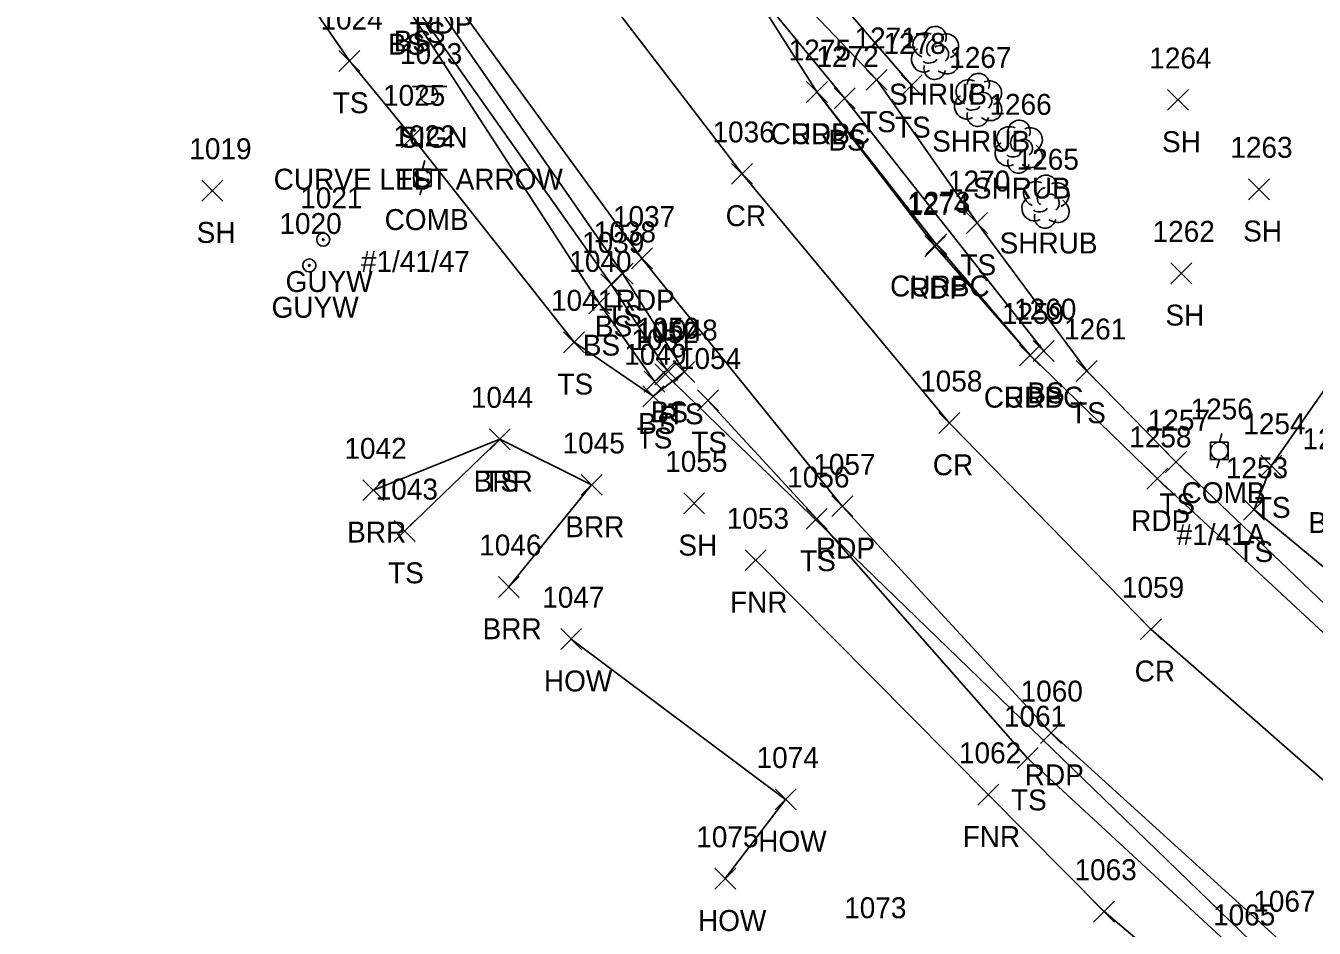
# Model space of a CAD drawing. Extents: x 1761340 to 1763889, y 696770 to 706023.
# Drawn here: x 1761355.7 to 1761478.8, y 700913.9 to 701000.1 of the extents above; entities that cross this region are included whole.
import ezdxf

# ---------------------------------------------------------------- set-up
doc = ezdxf.new("R2010")
doc.units = 0
for name, color, linetype in [('D_A', 7, 'Continuous'), ('D_I', 7, 'Continuous'), ('D_TIC', 7, 'Continuous'), ('DCP', 7, 'Continuous'), ('L_A', 7, 'Continuous'), ('L_I', 7, 'Continuous'), ('L_TIC', 7, 'Continuous'), ('LABL', 7, 'Continuous'), ('LBC', 7, 'Continuous'), ('LELB', 7, 'Continuous'), ('LFNC', 7, 'Continuous'), ('LSH', 7, 'Continuous'), ('P_A', 7, 'Continuous'), ('P_I', 7, 'Continuous'), ('P_TIC', 7, 'Continuous'), ('PET', 7, 'Continuous'), ('PRC', 7, 'Continuous'), ('R_A', 7, 'Continuous'), ('R_I', 7, 'Continuous'), ('R_TIC', 7, 'Continuous'), ('RC', 7, 'Continuous'), ('S_A', 7, 'Continuous'), ('S_C', 7, 'Continuous'), ('S_I', 7, 'Continuous'), ('SSGN', 7, 'Continuous'), ('U_A', 7, 'Continuous'), ('U_C', 7, 'Continuous'), ('U_I', 7, 'Continuous'), ('UP', 7, 'Continuous'), ('UPGW', 7, 'Continuous')]:
    doc.layers.add(name, color=color, linetype=linetype)

msp = doc.modelspace()

# ---------------------------------------------------------------- linework, layer by layer
at = {"layer": 'D_TIC'}
for points in [[(1761415.81, 700965.84), (1761417.81, 700967.84)], [(1761417.81, 700965.84), (1761415.81, 700967.84)]]:
    msp.add_lwpolyline(points, dxfattribs=at)
at = {"layer": 'DCP'}
msp.add_lwpolyline([(1761416.81, 700966.84), (1761514.71, 700872.07)], dxfattribs=at)
at = {"layer": 'L_TIC'}
for points in [[(1761385.62, 700995.79), (1761387.62, 700997.79)], [(1761387.62, 700995.79), (1761385.62, 700997.79)], [(1761436.01, 700993.98), (1761438.01, 700995.98)], [(1761438.01, 700993.98), (1761436.01, 700995.98)], [(1761439.34, 700993.46), (1761441.34, 700995.46)], [(1761441.34, 700993.46), (1761439.34, 700995.46)], [(1761432.93, 700992.22), (1761434.93, 700994.22)], [(1761434.93, 700992.22), (1761432.93, 700994.22)], [(1761464.78, 700992.07), (1761466.78, 700994.07)], [(1761466.78, 700992.07), (1761464.78, 700994.07)], [(1761391.6, 700988.5), (1761393.6, 700990.5)], [(1761393.6, 700988.5), (1761391.6, 700990.5)], [(1761372.53, 700983.4), (1761374.53, 700985.4)], [(1761374.53, 700983.4), (1761372.53, 700985.4)], [(1761472.53, 700983.53), (1761474.53, 700985.53)], [(1761474.53, 700983.53), (1761472.53, 700985.53)], [(1761445.59, 700980.31), (1761447.59, 700982.31)], [(1761447.59, 700980.31), (1761445.59, 700982.31)], [(1761411.73, 700975.45), (1761413.73, 700977.45)], [(1761413.73, 700975.45), (1761411.73, 700977.45)], [(1761465.1, 700975.5), (1761467.1, 700977.5)], [(1761467.1, 700975.5), (1761465.1, 700977.5)], [(1761410.63, 700974.45), (1761412.63, 700976.45)], [(1761412.63, 700974.45), (1761410.63, 700976.45)], [(1761409.48, 700972.63), (1761411.48, 700974.63)], [(1761411.48, 700972.63), (1761409.48, 700974.63)], [(1761407.08, 700968.91), (1761409.08, 700970.91)], [(1761409.08, 700968.91), (1761407.08, 700970.91)], [(1761451.96, 700968.07), (1761453.96, 700970.07)], [(1761453.96, 700968.07), (1761451.96, 700970.07)], [(1761415.96, 700966.25), (1761417.96, 700968.25)], [(1761417.96, 700966.25), (1761415.96, 700968.25)], [(1761417.63, 700966.07), (1761419.63, 700968.07)], [(1761419.63, 700966.07), (1761417.63, 700968.07)], [(1761456.07, 700966.17), (1761458.07, 700968.17)], [(1761458.07, 700966.17), (1761456.07, 700968.17)], [(1761414.77, 700965.15), (1761416.77, 700967.15)], [(1761416.77, 700965.15), (1761414.77, 700967.15)], [(1761414.77, 700965.15), (1761416.77, 700967.15)], [(1761416.77, 700965.15), (1761414.77, 700967.15)], [(1761414.65, 700963.75), (1761416.65, 700965.75)], [(1761416.65, 700963.75), (1761414.65, 700965.75)], [(1761414.65, 700963.75), (1761416.65, 700965.75)], [(1761416.65, 700963.75), (1761414.65, 700965.75)], [(1761419.87, 700963.35), (1761421.87, 700965.35)], [(1761421.87, 700963.35), (1761419.87, 700965.35)], [(1761399.99, 700959.64), (1761401.99, 700961.64)], [(1761401.99, 700959.64), (1761399.99, 700961.64)], [(1761399.99, 700959.64), (1761401.99, 700961.64)], [(1761401.99, 700959.64), (1761399.99, 700961.64)], [(1761464.59, 700957.47), (1761466.59, 700959.47)], [(1761466.59, 700957.47), (1761464.59, 700959.47)], [(1761473.72, 700957.12), (1761475.72, 700959.12)], [(1761475.72, 700957.12), (1761473.72, 700959.12)], [(1761408.76, 700955.28), (1761410.76, 700957.28)], [(1761410.76, 700955.28), (1761408.76, 700957.28)], [(1761387.91, 700954.77), (1761389.91, 700956.77)], [(1761389.91, 700954.77), (1761387.91, 700956.77)], [(1761418.56, 700953.52), (1761420.56, 700955.52)], [(1761420.56, 700953.52), (1761418.56, 700955.52)], [(1761472.06, 700952.91), (1761474.06, 700954.91)], [(1761474.06, 700952.91), (1761472.06, 700954.91)], [(1761430.27, 700952.03), (1761432.27, 700954.03)], [(1761432.27, 700952.03), (1761430.27, 700954.03)], [(1761390.9, 700950.87), (1761392.9, 700952.87)], [(1761392.9, 700950.87), (1761390.9, 700952.87)], [(1761424.44, 700948.08), (1761426.44, 700950.08)], [(1761426.44, 700948.08), (1761424.44, 700950.08)], [(1761400.85, 700945.53), (1761402.85, 700947.53)], [(1761402.85, 700945.53), (1761400.85, 700947.53)], [(1761406.81, 700940.54), (1761408.81, 700942.54)], [(1761408.81, 700940.54), (1761406.81, 700942.54)], [(1761450.42, 700929.17), (1761452.42, 700931.17)], [(1761452.42, 700929.17), (1761450.42, 700931.17)], [(1761446.68, 700925.67), (1761448.68, 700927.67)], [(1761448.68, 700925.67), (1761446.68, 700927.67)], [(1761427.3, 700925.22), (1761429.3, 700927.22)], [(1761429.3, 700925.22), (1761427.3, 700927.22)], [(1761421.53, 700917.65), (1761423.53, 700919.65)], [(1761423.53, 700917.65), (1761421.53, 700919.65)], [(1761457.72, 700914.5), (1761459.72, 700916.5)], [(1761459.72, 700914.5), (1761457.72, 700916.5)]]:
    msp.add_lwpolyline(points, dxfattribs=at)
at = {"layer": 'LABL'}
msp.add_lwpolyline([(1761388.91, 700955.77), (1761400.99, 700960.64), (1761409.76, 700956.28), (1761401.85, 700946.53)], dxfattribs=at)
at = {"layer": 'LBC'}
msp.add_lwpolyline([(1761407.81, 700941.54), (1761428.3, 700926.22), (1761422.53, 700918.65)], dxfattribs=at)
at = {"layer": 'LELB'}
for points in [[(1761440.34, 700994.46), (1761428.93, 701007.72), (1761425.32, 701020.81), (1761405.58, 701045), (1761388.99, 701070.94)], [(1761510.82, 700921.94), (1761487.03, 700937.99), (1761465.59, 700958.47), (1761457.07, 700967.17), (1761446.59, 700981.31), (1761437.01, 700994.98), (1761426.19, 701006.36), (1761420.48, 701017.58), (1761403.34, 701042.42), (1761383.02, 701066.87)], [(1761360.86, 701050.4), (1761380.33, 701022.73), (1761393.97, 701003.51), (1761412.73, 700976.45), (1761418.63, 700967.07), (1761415.65, 700964.75)], [(1761359.9, 701049.49), (1761378.89, 701021.46), (1761392.41, 701002.69), (1761411.63, 700975.45), (1761416.96, 700967.25), (1761415.77, 700966.15)], [(1761357.7, 701048.72), (1761378.05, 701020.95), (1761391.86, 701002.38), (1761410.48, 700973.63), (1761415.77, 700966.15)], [(1761355.69, 701047.71), (1761364.73, 701030.03), (1761371.68, 701018.45), (1761386.62, 700996.79), (1761392.6, 700989.5), (1761408.08, 700969.91), (1761415.65, 700964.75)], [(1761452.96, 700969.07), (1761433.93, 700993.22), (1761424.05, 701005.24)], [(1761506.71, 700926.07), (1761489.79, 700940.08), (1761473.06, 700953.91), (1761474.72, 700958.12), (1761484.47, 700972.09)], [(1761420.87, 700964.35), (1761431.27, 700953.03), (1761451.42, 700930.17), (1761471.96, 700911.18)], [(1761391.9, 700951.87), (1761400.99, 700960.64)]]:
    msp.add_lwpolyline(points, dxfattribs=at)
at = {"layer": 'LFNC'}
msp.add_lwpolyline([(1761425.44, 700949.08), (1761447.68, 700926.67), (1761458.72, 700915.5), (1761471.96, 700904.31)], dxfattribs=at)
at = {"layer": 'LSH'}
for p, q in [((1761442.55, 700997.61), (1761442.55, 700997.61)), ((1761442.55, 700997.61), (1761442.55, 700997.61)), ((1761446.67, 700993.12), (1761446.67, 700993.12)), ((1761446.67, 700993.12), (1761446.67, 700993.12)), ((1761450.56, 700988.64), (1761450.56, 700988.64)), ((1761450.56, 700988.64), (1761450.56, 700988.64)), ((1761453.11, 700983.39), (1761453.11, 700983.39)), ((1761453.11, 700983.39), (1761453.11, 700983.39))]:
    msp.add_line(p, q, dxfattribs=at)
for centre in [(1761442.6, 700999.04), (1761446.72, 700994.55), (1761450.61, 700990.07), (1761453.16, 700984.83)]:
    msp.add_arc(centre, 1.05, 335.5272, 180.9563, dxfattribs=at)
for centre, major_axis, ratio, start_param, end_param in [((1761441.76, 700998.27), (1.21, -0.51), 0.895232, 1.570796, 4.712389), ((1761442.34, 700998.06), (-0.208, -0.792), 0.645439, 3.141593, 6.283185), ((1761443.59, 700998.19), (-1.14, -0.48), 0.949671, 1.570796, 4.712389), ((1761441.47, 700996.9), (0.58, -1.04), 0.959034, 3.141593, 6.283185), ((1761443.05, 700997.44), (-0.5, 0.667), 0.989748, 3.141593, 6.283185), ((1761443.55, 700996.77), (-1.09, 0.79), 0.841452, 1.570796, 4.712389), ((1761442.55, 700996.11), (0.26, 1.06), 0.942809, 1.570796, 4.712389), ((1761442.09, 700996.86), (-0.625, -0.083), 0.423636, 0, 3.141593), ((1761445.88, 700993.79), (1.21, -0.51), 0.895232, 1.570796, 4.712389), ((1761447.71, 700993.7), (-1.14, -0.48), 0.949671, 1.570796, 4.712389), ((1761446.46, 700993.58), (-0.208, -0.792), 0.645439, 3.141593, 6.283185), ((1761447.17, 700992.95), (-0.5, 0.667), 0.989748, 3.141593, 6.283185), ((1761445.59, 700992.41), (0.58, -1.04), 0.959034, 3.141593, 6.283185), ((1761447.67, 700992.29), (-1.09, 0.79), 0.841452, 1.570796, 4.712389), ((1761446.67, 700991.62), (0.26, 1.06), 0.942809, 1.570796, 4.712389), ((1761446.21, 700992.37), (-0.625, -0.083), 0.423636, 0, 3.141593), ((1761449.77, 700989.31), (1.21, -0.51), 0.895232, 1.570796, 4.712389), ((1761451.6, 700989.22), (-1.14, -0.48), 0.949671, 1.570796, 4.712389), ((1761449.48, 700987.93), (0.58, -1.04), 0.959034, 3.141593, 6.283185), ((1761450.35, 700989.1), (-0.208, -0.792), 0.645439, 3.141593, 6.283185), ((1761451.06, 700988.47), (-0.5, 0.667), 0.989748, 3.141593, 6.283185), ((1761450.1, 700987.89), (-0.625, -0.083), 0.423636, 0, 3.141593), ((1761451.56, 700987.81), (-1.09, 0.79), 0.841452, 1.570796, 4.712389), ((1761450.56, 700987.14), (0.26, 1.06), 0.942809, 1.570796, 4.712389), ((1761452.32, 700984.06), (1.21, -0.51), 0.895232, 1.570796, 4.712389), ((1761454.15, 700983.97), (-1.14, -0.48), 0.949671, 1.570796, 4.712389), ((1761452.9, 700983.85), (-0.208, -0.792), 0.645439, 3.141593, 6.283185), ((1761453.61, 700983.22), (-0.5, 0.667), 0.989748, 3.141593, 6.283185), ((1761452.03, 700982.68), (0.58, -1.04), 0.959034, 3.141593, 6.283185), ((1761452.65, 700982.64), (-0.625, -0.083), 0.423636, 0, 3.141593), ((1761454.11, 700982.56), (-1.09, 0.79), 0.841452, 1.570796, 4.712389), ((1761453.11, 700981.89), (0.26, 1.06), 0.942809, 1.570796, 4.712389)]:
    msp.add_ellipse(centre, major_axis=major_axis, ratio=ratio, start_param=start_param, end_param=end_param, dxfattribs=at)
at = {"layer": 'P_TIC'}
for points in [[(1761430.29, 700992.83), (1761432.29, 700994.83)], [(1761432.29, 700992.83), (1761430.29, 700994.83)], [(1761423.14, 700985), (1761425.14, 700987)], [(1761425.14, 700985), (1761423.14, 700987)], [(1761441.59, 700978.07), (1761443.59, 700980.07)], [(1761443.59, 700978.07), (1761441.59, 700980.07)], [(1761413.57, 700976.92), (1761415.57, 700978.92)], [(1761415.57, 700976.92), (1761413.57, 700978.92)], [(1761450.66, 700967.66), (1761452.66, 700969.66)], [(1761452.66, 700967.66), (1761450.66, 700969.66)], [(1761442.93, 700961.2), (1761444.93, 700963.2)], [(1761444.93, 700961.2), (1761442.93, 700963.2)], [(1761462.82, 700955.86), (1761464.82, 700957.86)], [(1761464.82, 700955.86), (1761462.82, 700957.86)], [(1761432.71, 700953.24), (1761434.71, 700955.24)], [(1761434.71, 700953.24), (1761432.71, 700955.24)], [(1761462.21, 700941.49), (1761464.21, 700943.49)], [(1761464.21, 700941.49), (1761462.21, 700943.49)], [(1761452.66, 700931.57), (1761454.66, 700933.57)], [(1761454.66, 700931.57), (1761452.66, 700933.57)]]:
    msp.add_lwpolyline(points, dxfattribs=at)
at = {"layer": 'PET'}
for points in [[(1761565.69, 700887.32), (1761551.93, 700894.01), (1761537.2, 700902.21), (1761507.2, 700921.56), (1761485.83, 700936.45), (1761463.82, 700956.86), (1761451.66, 700968.66), (1761442.59, 700979.07), (1761431.29, 700993.83), (1761424.05, 701005.24), (1761416.58, 701016.18), (1761400.04, 701039.88), (1761381.47, 701065.28)], [(1761361.55, 701051.07), (1761381.35, 701023.89), (1761395.32, 701004.39), (1761414.57, 700977.92), (1761433.71, 700954.24), (1761453.66, 700932.57), (1761475.8, 700912.49), (1761486.98, 700903.81), (1761500.92, 700894.3), (1761527.65, 700879.06), (1761551.01, 700866.82), (1761575.84, 700857.11)]]:
    msp.add_lwpolyline(points, dxfattribs=at)
at = {"layer": 'PRC'}
msp.add_lwpolyline([(1761371.66, 701058.14), (1761390.63, 701031.26), (1761404.65, 701011.45), (1761424.14, 700986), (1761443.93, 700962.2), (1761463.21, 700942.49), (1761486.68, 700921.95), (1761508.06, 700906.42), (1761533.51, 700890.82), (1761557.04, 700878.89), (1761580.26, 700869.03), (1761600.69, 700862.06)], dxfattribs=at)
at = {"layer": 'R_TIC'}
for points in [[(1761430.29, 700992.83), (1761432.29, 700994.83)], [(1761432.29, 700992.83), (1761430.29, 700994.83)], [(1761441.69, 700978.28), (1761443.69, 700980.28)], [(1761443.69, 700978.28), (1761441.69, 700980.28)], [(1761450.66, 700967.66), (1761452.66, 700969.66)], [(1761452.66, 700967.66), (1761450.66, 700969.66)]]:
    msp.add_lwpolyline(points, dxfattribs=at)
at = {"layer": 'RC'}
msp.add_lwpolyline([(1761451.66, 700968.66), (1761442.69, 700979.28), (1761431.29, 700993.83)], dxfattribs=at)
at = {"layer": 'SSGN'}
for p, q in [((1761392.6, 700994.35), (1761395.93, 700994.35)), ((1761394.25, 700993.52), (1761394.25, 700993.52))]:
    msp.add_line(p, q, dxfattribs=at)
msp.add_circle((1761394.25, 700993.52), 0.833, dxfattribs=at)
at = {"layer": 'UP'}
for p, q in [((1761392.76, 700984.79), (1761392.76, 700986.46)), ((1761392.76, 700986.46), (1761394.43, 700986.46)), ((1761393.84, 700987.29), (1761393.59, 700986.46)), ((1761394.43, 700986.46), (1761394.43, 700984.79)), ((1761393.59, 700985.63), (1761393.59, 700985.63)), ((1761394.43, 700984.79), (1761392.76, 700984.79)), ((1761393.34, 700983.96), (1761393.59, 700984.79)), ((1761469.99, 700961.19), (1761469.74, 700960.36)), ((1761468.91, 700958.69), (1761468.91, 700960.36)), ((1761468.91, 700960.36), (1761470.57, 700960.36)), ((1761469.74, 700959.53), (1761469.74, 700959.53)), ((1761470.57, 700960.36), (1761470.57, 700958.69)), ((1761470.57, 700958.69), (1761468.91, 700958.69)), ((1761469.49, 700957.86), (1761469.74, 700958.69))]:
    msp.add_line(p, q, dxfattribs=at)
for centre in [(1761393.59, 700985.63), (1761469.74, 700959.53)]:
    msp.add_circle(centre, 0.833, dxfattribs=at)
at = {"layer": 'UPGW'}
for centre, radius in [((1761384.12, 700979.71), 0.625), ((1761384.12, 700979.71), 0.0833), ((1761382.79, 700977.25), 0.625), ((1761382.79, 700977.25), 0.0833)]:
    msp.add_circle(centre, radius, dxfattribs=at)

# ---------------------------------------------------------------- texts
at = {"layer": 'D_A'}
msp.add_text('P', height=2, dxfattribs=at).set_placement((1761416.19, 700961.84))
at = {"layer": 'D_I'}
msp.add_text('1052', height=2, dxfattribs=at).set_placement((1761414.04, 700969.84))
at = {"layer": 'L_A'}
for s, p in [('TS', (1761392.38, 700998.51)), ('BS', (1761390.3, 700997.38)), ('BS', (1761390.85, 700997.69)), ('TS', (1761385.03, 700991.79)), ('SHRUB', (1761438.18, 700992.61)), ('TS', (1761435.42, 700989.98)), ('TS', (1761438.75, 700989.46)), ('BS', (1761432.37, 700988.22)), ('SHRUB', (1761442.3, 700988.12)), ('SH', (1761464.26, 700988.07)), ('TS', (1761391.01, 700984.5)), ('SHRUB', (1761446.19, 700983.64)), ('SH', (1761472.02, 700979.53)), ('SH', (1761372.02, 700979.4)), ('SHRUB', (1761448.74, 700978.39)), ('TS', (1761445, 700976.31)), ('TS', (1761411.14, 700971.45)), ('SH', (1761464.59, 700971.5)), ('BS', (1761410.07, 700970.45)), ('BS', (1761408.92, 700968.63)), ('TS', (1761406.49, 700964.91)), ('BS', (1761451.4, 700964.07)), ('BS', (1761415.4, 700962.25)), ('BS', (1761414.21, 700961.15)), ('BS', (1761414.21, 700961.15)), ('TS', (1761417.04, 700962.07)), ('TS', (1761455.48, 700962.17)), ('TS', (1761414.06, 700959.75)), ('TS', (1761414.06, 700959.75)), ('TS', (1761419.28, 700959.35)), ('BRR', (1761398.48, 700955.64)), ('TS', (1761399.4, 700955.64)), ('TS', (1761464, 700953.47)), ('TS', (1761473.13, 700953.12)), ('BRR', (1761407.24, 700951.28)), ('BS', (1761478.26, 700951.68)), ('BRR', (1761386.4, 700950.77)), ('SH', (1761418.05, 700949.52)), ('TS', (1761471.47, 700948.91)), ('TS', (1761429.68, 700948.03)), ('TS', (1761390.31, 700946.87)), ('FNR', (1761422.98, 700944.08)), ('BRR', (1761399.34, 700941.53)), ('HOW', (1761405.2, 700936.54)), ('TS', (1761449.83, 700925.17)), ('FNR', (1761445.21, 700921.67)), ('HOW', (1761425.68, 700921.22)), ('HOW', (1761419.92, 700913.65))]:
    msp.add_text(s, height=2, dxfattribs=at).set_placement(p)
at = {"layer": 'L_I'}
for s, p in [('1024', (1761383.85, 700999.79)), ('1271', (1761434.88, 700997.98)), ('1278', (1761437.65, 700997.46)), ('1272', (1761431.24, 700996.22)), ('1267', (1761443.93, 700996.12)), ('1264', (1761463.04, 700996.07)), ('1025', (1761389.83, 700992.5)), ('1266', (1761447.77, 700991.64)), ('1019', (1761371.32, 700987.4)), ('1263', (1761470.79, 700987.53)), ('1265', (1761450.37, 700986.39)), ('1270', (1761443.81, 700984.31)), ('1038', (1761409.96, 700979.45)), ('1262', (1761463.36, 700979.5)), ('1039', (1761408.85, 700978.45)), ('1040', (1761407.63, 700976.63)), ('1041', (1761405.88, 700972.91)), ('1260', (1761450.13, 700972.07)), ('1050', (1761414.1, 700970.25)), ('1048', (1761415.86, 700970.07)), ('1261', (1761454.9, 700970.17)), ('1051', (1761413.56, 700969.15)), ('1051', (1761413.56, 700969.15)), ('1049', (1761412.88, 700967.75)), ('1049', (1761412.88, 700967.75)), ('1054', (1761418.1, 700967.35)), ('1044', (1761398.22, 700963.64)), ('1044', (1761398.22, 700963.64)), ('1257', (1761462.9, 700961.47)), ('1254', (1761472.03, 700961.12)), ('1042', (1761386.14, 700958.77)), ('1045', (1761406.98, 700959.28)), ('1251', (1761477.69, 700959.68)), ('1055', (1761416.79, 700957.52)), ('1056', (1761428.45, 700956.03)), ('1253', (1761470.36, 700956.91)), ('1043', (1761389.13, 700954.87)), ('1053', (1761422.67, 700952.08)), ('1046', (1761399.02, 700949.53)), ('1047', (1761405.04, 700944.54)), ('1061', (1761449.16, 700933.17)), ('1074', (1761425.52, 700929.22)), ('1062', (1761444.86, 700929.67)), ('1075', (1761419.76, 700921.65)), ('1063', (1761455.9, 700918.5)), ('1073', (1761433.89, 700914.87)), ('1065', (1761469.14, 700914.18))]:
    msp.add_text(s, height=2, dxfattribs=at).set_placement(p)
at = {"layer": 'P_A'}
for s, p in [('RDP', (1761392.81, 700999.39)), ('RDP', (1761428.78, 700988.83)), ('CR', (1761422.57, 700981)), ('RDP', (1761440.08, 700974.07)), ('RDP', (1761412.06, 700972.92)), ('RDP', (1761449.15, 700963.66)), ('CR', (1761442.36, 700957.2)), ('RDP', (1761461.31, 700951.86)), ('RDP', (1761431.2, 700949.24)), ('CR', (1761461.65, 700937.49)), ('RDP', (1761451.15, 700927.57))]:
    msp.add_text(s, height=2, dxfattribs=at).set_placement(p)
at = {"layer": 'P_I'}
for s, p in [('1275', (1761428.59, 700996.83)), ('1036', (1761421.31, 700989)), ('1274', (1761439.9, 700982.07)), ('1037', (1761411.8, 700980.92)), ('1259', (1761448.96, 700971.66)), ('1058', (1761441.15, 700965.2)), ('1258', (1761461.13, 700959.86)), ('1057', (1761430.94, 700957.24)), ('1059', (1761460.43, 700945.49)), ('1060', (1761450.75, 700935.57)), ('1067', (1761472.98, 700915.49))]:
    msp.add_text(s, height=2, dxfattribs=at).set_placement(p)
at = {"layer": 'R_A'}
for p in [(1761426.87, 700988.83), (1761438.28, 700974.28), (1761447.24, 700963.66)]:
    msp.add_text('CURBC', height=2, dxfattribs=at).set_placement(p)
at = {"layer": 'R_I'}
for s, p in [('1275', (1761428.59, 700996.83)), ('1273', (1761440, 700982.28)), ('1259', (1761448.96, 700971.66)), ('1067', (1761472.98, 700915.49))]:
    msp.add_text(s, height=2, dxfattribs=at).set_placement(p)
at = {"layer": 'S_A'}
msp.add_text('SIGN', height=2, dxfattribs=at).set_placement((1761391.38, 700988.49))
at = {"layer": 'S_C'}
msp.add_text('CURVE LEFT ARROW', height=2, dxfattribs=at).set_placement((1761379.38, 700984.49))
at = {"layer": 'S_I'}
msp.add_text('1023', height=2, dxfattribs=at).set_placement((1761391.45, 700996.49))
at = {"layer": 'U_A'}
for s, p in [('COMB', (1761389.98, 700980.63)), ('GUYW', (1761380.52, 700974.71)), ('GUYW', (1761379.18, 700972.25)), ('COMB', (1761466.13, 700954.53))]:
    msp.add_text(s, height=2, dxfattribs=at).set_placement(p)
at = {"layer": 'U_C'}
for s, p in [('#1/41/47', (1761387.72, 700976.63)), ('#1/41A', (1761465.66, 700950.53))]:
    msp.add_text(s, height=2, dxfattribs=at).set_placement(p)
at = {"layer": 'U_I'}
for s, p in [('1022', (1761390.82, 700988.63)), ('1021', (1761381.92, 700982.71)), ('1020', (1761379.93, 700980.25)), ('1256', (1761466.99, 700962.53))]:
    msp.add_text(s, height=2, dxfattribs=at).set_placement(p)

doc.saveas('drawing.dxf')
